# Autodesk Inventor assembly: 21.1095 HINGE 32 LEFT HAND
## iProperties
Created: 2007-01
Part Number: 21.1095 HINGE 32 LEFT HAND
Document SubType Name: Assembly
Designer: Andy Moles
Author: Andy Moles
